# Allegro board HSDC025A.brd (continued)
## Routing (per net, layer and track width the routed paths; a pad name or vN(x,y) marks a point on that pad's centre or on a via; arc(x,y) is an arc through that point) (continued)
N53375: length 11.3
  TOP w0.14: C5.1 52.28,24.89 45.61,24.89 44.8,24.08 41.85,24.08 U1.40
N53379: length 11.3
  TOP w0.14: U1.39 41.85,23.82 44.9,23.82 45.72,24.64 52.28,24.64 C7.1
N53383: length 11.1
  TOP w0.14: U1.37 41.85,22.88 45.63,22.88 45.92,23.17 50.16,23.17 50.16,23.17 52.28,23.17 C10.1
N53387: length 11.1
  TOP w0.14: U1.36 41.85,22.62 45.73,22.62 46.02,22.91 50.06,22.91 50.06,22.91 52.28,22.91 C12.1
N53391: length 11.1
  TOP w0.14: U1.34 41.85,21.68 46.12,21.68 46.36,21.44 52.28,21.44 C14.1
N53395: length 11.1
  TOP w0.14: U1.33 41.85,21.42 46.02,21.42 46.25,21.19 52.28,21.19 C16.1
N53399: length 11.3
  TOP w0.14: U1.31 41.85,20.48 43.61,20.48 44.37,19.71 52.28,19.71 C18.1
N53403: length 11.3
  TOP w0.14: C20.1 52.28,19.46 44.27,19.46 43.51,20.22 41.85,20.22 U1.30
N54909: length 3.6
  BOTTOM w0.102: U6.K9 U6.L9 27.13,37.86 26.84,37.58 26.84,37.34 25.85,36.35
  BOTTOM w0.241: R37.1 25.45,35.94 25.85,36.35
N54981: length 2.6
  BOTTOM w0.102: U6.K10 U6.L10 26.63,37.86 25.54,36.78 R38.1
N60753: length 2
  BOTTOM w0.241: R22.1 18.27,7.77 18.31,7.81 J1.1
N61165: length 2.5
  BOTTOM w0.241: R28.1 27.86,7.83 27.9,7.88 J2.1
N61173: length 1.9
  BOTTOM w0.241: JMP3.4 46.18,41.33 46.21,41.36 R26.1
N61517: length 2
  BOTTOM w0.241: J3.1 35.71,7.92 35.69,7.9 R33.1
N61661: length 1.7
  BOTTOM w0.241: R35.1 10.6,7.82 10.62,7.8 J4.1
N62024: length 18.2
  TOP w0.14: v2(42.87,13.51) 42.78,13.6 42.78,14.03 43.72,14.97 46.66,14.97 48.22,16.53 51.54,16.53 R6.1 ; v2(41.63,16.29) 41.54,16.37 41.54,16.43 41.5,16.48 41.5,16.87 40.81,17.56 40.81,18.98 U1.27
  BOTTOM w0.14: v2(41.63,16.29) 41.54,16.2 41.54,15.91 41.78,15.67 42.15,15.67 42.56,15.27 42.56,14.87 42.96,14.47 R13.1 43.19,14.46 43.19,14.05 42.87,13.73 v2(42.87,13.51)
N62031: length 18.2
  TOP w0.14: v2(41.19,16.29) 41.19,16.3 41.24,16.35 41.24,16.76 40.55,17.46 40.55,18.98 U1.26 ; v2(42.44,13.51) 42.52,13.6 42.52,14.14 43.61,15.22 46.55,15.22 48.11,16.78 51.63,16.78 R8.1
  BOTTOM w0.14: v2(41.19,16.29) 41.28,16.2 41.28,15.81 41.68,15.42 42.05,15.42 42.3,15.16 42.3,14.96 42.14,14.8 R12.1 42.14,14.01 42.44,13.72 v2(42.44,13.51)
N62627: length 7.5
  TOP w0.241: U1.25 40.08,16.6 40.33,16.35 40.33,13.12 40.12,12.91 R11.2
N62636: length 4.3
  TOP w0.241: U1.24 39.68,17.7 39,17.02 R7.2
N63203: length 9.2
  TOP w0.241: R41.1 34.14,46.86 34.26,46.73 34.26,43.61 33.32,42.67 30.86,42.67 v2(30.18,41.99)
  BOTTOM w0.102: U6.B2 v2(30.18,41.99)
N63233: length 8
  TOP w0.241: R43.1 33,45.39 33.76,44.63 v2(33.76,43.89)
  BOTTOM w0.102: U6.C2 30.88,42.19 31.43,42.19 31.73,42.49 32.46,42.49 32.7,42.74 32.88,42.74 32.89,42.75
  BOTTOM w0.241: 32.89,42.75 33.16,42.75 33.76,43.35 v2(33.76,43.89)
N63241: length 5.4
  TOP w0.241: v1(22.38,41.77) 22.04,42.11 R44.1
  BOTTOM w0.102: 24.46,41.58 25.4,41.58 25.8,41.18 26.36,41.18 26.39,41.21 26.4,41.21 U6.D10
  BOTTOM w0.241: 24.46,41.58 22.57,41.58 v1(22.38,41.77)
N63249: length 15
  TOP w0.241: v2(27,41.94) 26.72,41.65 26.72,40.93 23.93,38.15 23.93,35.63 26.54,33.02 29.35,33.02 29.36,33.02 R40.2
  BOTTOM w0.102: U6.C10 v2(27,41.94)
N73513: length 21.9
  TOP w0.14: C1.2 49.23,38.62 49.23,36.56 47.42,34.75 41.64,34.75 39.19,32.3 39.19,26.09 38.81,25.71 38.81,24.92 U1.7
N73520: length 21.9
  TOP w0.14: U1.8 38.55,24.92 38.55,25.81 38.94,26.2 38.94,32.41 41.53,35 47.31,35 48.97,36.66 48.97,38.62 C9.2
N75829: length 5.4
  TOP w0.241: v1(22.45,39.98) R42.2
  BOTTOM w0.102: 24.46,40.78 25.13,40.78 25.22,40.69 26.38,40.69 U6.E10
  BOTTOM w0.241: v1(22.45,39.98) 23.25,40.78 24.46,40.78
N78382: length 1.8
  BOTTOM w0.241: R66.2 13.71,38.95 13.68,38.97 J7.1
N78490: length 1.7
  BOTTOM w0.241: J7.3 13.68,41.51 13.7,41.5 R70.2
N79273: length 9.2
  TOP w0.241: R49.2 37.17,35.95 36.74,35.52 31.82,35.52 v2(30.38,36.96)
  BOTTOM w0.102: U6.K3 30.38,38.18 v2(30.38,36.96)
N79277: length 9.5
  TOP w0.241: R48.2 31.62,34.9 v2(29.79,36.73)
  BOTTOM w0.102: v2(29.79,36.73) 29.79,37.06 30.13,37.39 U6.L3
N79281: length 4.9
  TOP w0.241: v2(33.9,36.65) R47.2
  BOTTOM w0.102: U6.K2 30.88,38.69 31.52,38.69 31.94,38.28 32.36,38.28 32.89,37.74 32.89,37.66
  BOTTOM w0.241: v2(33.9,36.65) 32.89,37.66
N79285: length 8
  TOP w0.241: v2(30.92,37.22) 32.06,36.09 35.45,36.09 36.4,37.03 R45.2
  BOTTOM w0.102: v2(30.92,37.22) 30.92,37.57 30.63,37.86 U6.L2
N80574: length 5.1
  TOP w0.241: R51.1 v1(22.4,38.91)
  BOTTOM w0.102: 24.46,40.34 24.56,40.44 U6.F11
  BOTTOM w0.241: v1(22.4,38.91) 23.83,40.34 24.46,40.34
N80581: length 4.8
  TOP w0.241: v1(22.43,40.88) 22.26,41.05 R50.1
  BOTTOM w0.102: U6.E11 25.5,40.94 25.21,41.23 24.46,41.23
  BOTTOM w0.241: 24.46,41.23 24.4,41.17 22.72,41.17 v1(22.43,40.88)
N81425: length 6.8
  TOP w0.241: v2(36.12,38.47) R39.1
  BOTTOM w0.102: 32.89,40.17 32.75,40.17 32.73,40.19 30.88,40.19 U6.G2
  BOTTOM w0.241: 32.89,40.17 32.92,40.17 34.63,38.46 v2(36.12,38.47)
N85567: length 6.5
  TOP w0.241: R53.2 36.61,40.62 36.26,40.62 v2(36.07,40.63)
  BOTTOM w0.102: 32.89,41.23 32.68,41.45 32.18,41.45 31.91,41.18 30.87,41.18 U6.E2
  BOTTOM w0.241: v2(36.07,40.63) 35.48,41.02 35.15,41.02 34.94,41.23 32.89,41.23
N85571: length 6.7
  TOP w0.241: R60.2 36.61,39.57 v2(36.07,39.57)
  BOTTOM w0.102: 32.89,40.86 32.6,40.86 32.44,40.69 30.88,40.69 U6.F2
  BOTTOM w0.241: v2(36.07,39.57) 34.58,40.86 32.89,40.86
N88590: length 7.3
  TOP w0.241: R87.1 22.16,37.6 v1(22.4,37.85) R52.1
  BOTTOM w0.102: 24.46,39.8 24.66,40.01 25.43,40.01 25.58,40.16 25.93,40.16 25.95,40.18 26.16,40.18 26.16,40.18 26.37,40.18 U6.F10
  BOTTOM w0.241: 24.46,39.8 24.36,39.8 v1(22.4,37.85)
N89051: length 2.3
  TOP w0.241: SW1.6 v1(15.6,56.16)
  BOTTOM w0.241: R62.1 16.12,56.16 16.12,56.16 v1(15.6,56.16)
N89058: length 2.3
  TOP w0.241: SW1.7 v1(15.6,54.89)
  BOTTOM w0.241: R63.1 16.12,54.89 16.12,54.89 v1(15.6,54.89)
N89065: length 2.3
  TOP w0.241: SW1.8 v1(15.57,53.62)
  BOTTOM w0.241: v1(15.57,53.62) 16.12,53.62 16.12,53.62 R64.1
N92164: length 3.2
  TOP w0.241: R61.1 28.64,44.13 28.63,44.12 v2(28.63,41.86)
  BOTTOM w0.102: U6.D6 v2(28.63,41.86)
N95070: length 1.3
  TOP w0.241: C27.1 28.12,39.47 28.13,39.47 v2(28.13,39.07)
  BOTTOM w0.102: U6.H7 v2(28.13,39.07)
N98885: length 1.6
  TOP w0.241: D2.2 54.03,38.2 54.15,38.32 R77.1
N16698171: length 4
  TOP w0.241: v1(57.51,35.15) 57.61,35.26 FB1.1
  BOTTOM w0.241: R75.2 58.47,36.12 v1(57.51,35.15) 56.59,36.07 R76.2
N16698282: length 4.4
  TOP w0.241: R46.1 27.41,37.29 28.63,38.51 v2(28.63,39.09)
  BOTTOM w0.102: U6.H6 v2(28.63,39.09)
N16700173: length 2.2
  TOP w0.241: R78.1 62.15,60.93 61.67,61.42 D4.2
N16705873: length 14.5
  TOP w0.14: U1.12 37.91,22.88 29.46,22.88 29.04,22.46 24.14,22.46 23.85,22.75 C8.2
N16705894: length 14.5
  TOP w0.14: C11.2 23.85,21.91 24.14,22.2 29.14,22.2 29.56,22.62 37.9,22.62 U1.13
N16705898: length 14.7
  TOP w0.14: C13.2 24.15,20.73 29.62,20.73 30.57,21.68 37.91,21.68 U1.15
N16705902: length 14.7
  TOP w0.14: U1.16 37.9,21.42 30.67,21.42 29.73,20.48 24.15,20.48 C15.2
N16750118: length 3.6
  BOTTOM w0.241: U9.5 69.57,37.81 69.48,37.91 R81.1 R80.2
N16816893: length 2
  BOTTOM w0.241: R19.1 15.97,17.09 15.94,17.12 JMP1.2
N16816902: length 2.1
  BOTTOM w0.241: R21.1 16,14.52 15.94,14.58 JMP1.4
N16816999: length 1.9
  BOTTOM w0.241: R24.1 46.2,43.84 46.18,43.87 JMP3.2
N16817208: length 2.1
  BOTTOM w0.241: R29.1 58.79,8.31 58.71,8.38 JMP5.2
N16817217: length 2.1
  BOTTOM w0.241: JMP5.4 58.71,5.84 58.79,5.77 R31.1
N16817279: length 2
  BOTTOM w0.241: JMP7.2 48.49,8.38 48.51,8.37 R34.1
N16817288: length 1.9
  BOTTOM w0.241: R36.1 48.56,5.77 48.49,5.84 JMP7.4
N16817349: length 1.5
  BOTTOM w0.241: R30.1 68.31,8.31 68.23,8.38 JMP6.2
N16817418: length 1.5
  BOTTOM w0.241: R32.1 68.67,5.95 68.23,5.84 JMP6.4
N16817489: length 2
  BOTTOM w0.241: JMP4.4 43.95,53.05 44,53 R27.1
N16817492: length 2
  BOTTOM w0.241: JMP4.2 43.95,55.59 44.1,55.43 R25.1
N16817504: length 2.1
  BOTTOM w0.241: R20.1 28.74,17.95 28.67,17.88 JMP2.2
N16817513: length 1.7
  BOTTOM w0.241: JMP2.4 29.66,14.35 29.71,14.3 R23.1

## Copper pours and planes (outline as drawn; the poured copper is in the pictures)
GND on TOP: 31.55,37.19 31.55,37.65 31.91,38.01 32.95,38.01 33.25,38.3 33.25,38.66 33.99,38.66 34.37,39.04 35.67,39.04 35.67,37.39 35.23,36.96 34.67,36.96 34.62,37.01 34.62,37.95 34.52,38.05 33.48,38.05 32.59,37.16 31.57,37.16
GND on TOP: 37.92,34.62 37.92,37.62 37.39,38.15 37.39,40.94 39.22,40.94 39.22,34.59 37.95,34.59
GND on TOP: 24.62,45.2 24.62,44.59 23.93,43.9 23.93,41.3 22.97,41.3 22.97,45.2
GND on TOP: 57.4,42.96 53.45,42.96 52.86,42.37 52.86,40.72 53.87,39.7 54.48,39.7 55.98,41.2 55.98,41.22 57.4,41.22
GND on BOTTOM: 68.49,34.78 71.66,34.78 72.44,35.56 72.44,38.16 71.4,39.2 67.45,39.2 67,38.75 65.98,38.75 65.48,39.25 65.48,43.03 67.18,44.73 77.17,44.73 77.92,43.98 77.92,31.76 77.94,31.74 77.94,28.01 77.17,27.24 66.61,27.24 65.45,28.4 65.45,30.76 71.56,30.76 71.93,31.13 71.93,33.28 71.05,34.15 68.47,34.15 68.47,34.76
GND on BOTTOM: 7.92,26.98 1.43,26.98 0.68,26.22 0.68,16.4 1.14,15.93 7.17,15.93 8.3,17.06 8.3,18.02 7.88,18.44 4.18,18.44 4.18,24.44 4.81,25.06 7.87,25.06 7.97,25.16 7.97,26.93
GND on BOTTOM: 57.81,40.82 54.79,40.82 52.37,38.4 48.54,38.4 48.44,38.51 48.44,45.29 48.49,45.34 50.7,45.34 54.61,41.43 57.78,41.43 57.81,41.4
GND on BOTTOM: 27.48,42.57 27.48,41.91 27.05,41.48 27.05,39.78 27.43,39.78 27.48,39.73 27.48,39.27 27.43,39.22 27.05,39.22 27.05,38.91 27.79,38.91 27.79,39.8 28.98,39.8 28.98,38.91 29.79,38.91 29.79,39.57 29.36,39.57 29.26,39.67 29.26,40.87 29.26,40.87 29.26,41.01 29.2,41.07 27.76,41.07 27.76,42.57
GND on L2_GND, L5_GND: 0.64,0.64 0.64,67.74 79.12,67.74 79.12,0.64 ; 10 cut-outs
VBUS on TOP: 25.04,45.16 25.04,44.37 24.77,44.09 24.77,42.94 25.03,42.94 25.04,42.94 27,42.94 27,45.16
VBUS on TOP: 4.34,33.55 4.34,31.68 8.63,31.68 8.63,33.55
VBUS on BOTTOM: 0.98,67.39 15.56,67.39 15.56,67.39 17.81,67.39 17.81,65.24 17.73,65.17 15.93,65.17 14.61,63.85 14.61,56.76 12.67,54.83 9.76,54.83 8.54,53.61 8.54,31.7 0.98,31.7
VBUS on BOTTOM: 26.29,39.52 26.29,39.12 26.34,39.07 26.77,39.07 26.77,38.79 26.75,38.76 26.29,38.76 26.29,38.35 25.2,38.35 25.2,38.99 25.43,38.99 25.96,39.52
VBUS on BOTTOM: 26.77,42.29 26.77,43.26 27,43.48 27,43.79 26.24,43.79 26.24,43.51 26.49,43.26 26.49,42.29
VBUS on BOTTOM: 65.52,35.06 65.52,37.85 63.16,37.85 63.16,35.06
VBUS on L3_PWR: 18.31,37.41 19.23,36.5 21.49,36.5 23.87,38.88 23.87,41.42 26.19,41.42 26.19,43.83 26.16,43.86 26.16,47.52 34.85,56.2 62.75,56.2 64.04,54.91 64.04,39.7 65.38,38.37 65.38,36.6 65.31,36.54 62.09,36.54 61.44,37.19 61.44,40.11 49.72,51.83 34.14,51.83 27.03,44.71 27.03,36.35 25.15,34.47 14.4,34.47 14.39,34.46 8.73,34.46 8.62,34.35 8.62,31.63 4.38,31.63 4.31,31.69 4.31,36.46 5.27,37.41
VBUS_DS on TOP: 24.68,42.72 24.68,41.29 25.84,41.29 25.84,42.72
VBUS_DS on BOTTOM: 70.68,36.01 68.25,36.01 68.03,36.24 68.03,37.96 68.03,37.96 66.01,37.96 66,37.95 66,35.57 66.52,35.05 66.52,35.06 67.79,35.06 68.15,35.42 70.69,35.42 70.69,36
VBUS_DS on BOTTOM: 26.29,43.1 26.29,41.35 26.01,41.35 25.22,42.14 25.21,42.14 25.21,43.1
VBUS_DS on L3_PWR: 0.71,62.58 0.71,67.59 78.94,67.59 79.03,67.49 79.03,35.74 78.97,35.68 65.93,35.68 65.93,39.32 64.78,40.47 64.78,57.22 35.09,57.22 25.82,47.95 25.82,41.78 23.93,41.78 23.93,57.82 19.17,62.58 ; 8 cut-outs
VBUS_DS on L4_PWR: 24.84,40.72 26.21,39.34 27.15,39.34 27.23,39.42 27.23,39.6 27.15,39.67 26.72,39.67 25.84,40.55 25.84,43 25.71,43.14 24.92,43.14 24.84,43.06
VDDIO on L3_PWR: 32.48,43.66 32.48,41.98 31.68,41.18 31.68,39.01 34.56,36.13 34.56,30.73 31.96,30.73 31.04,31.66 31.04,43.25 31.49,43.7 32.44,43.7
VDDIO on L4_PWR: 51.2,32.9 51.2,30.3 50.72,29.81 41.55,29.81 36.27,35.09 34.04,35.09 32.7,33.76 32.7,31.82 37.22,27.3 51.55,27.3 53,28.76 53,33.32 52.99,33.33 51.63,33.33
3P3VCC on TOP: 55.55,36.68 55.55,40.16 58.52,40.16 58.52,37.37 56.59,37.37 56.59,36.68
3P3VCC on BOTTOM: 55.52,40.16 55.52,37.36 58.52,37.36 58.52,40.16
3P3VCC on L4_PWR: 57.31,40.41 57.31,35.38 62.21,30.47 62.21,16.79 61.61,16.19 41.09,16.19 40.4,15.5 40.4,13.87 41.01,13.26 64.19,13.26 65.53,14.6 65.53,32.02 60.45,37.1 60.45,40.37 60.41,40.41 ; 2 cut-outs
1064_VCC on BOTTOM: 57.73,34.06 57.73,30.05 59.55,30.05 59.55,34.06
1064_VCC on L3_PWR: 78.89,1.09 78.89,35.39 78.73,35.22 60.7,35.22 60.7,39.73 49.38,51.05 39.11,51.05 39.11,48.36 43.35,48.36 43.74,48.75 48.97,48.75 48.97,44.13 46.04,44.13 46.03,41.59 47.42,41.59 50.45,41.59 56.09,35.95 56.17,35.95 56.17,30.99 44.98,30.99 44.98,37.13 44.7,37.41 42.75,37.41 42.25,36.92 42.32,36.86 42.32,33.93 35.36,33.93 35.36,29.44 22.45,16.53 0.94,16.53 0.94,1.09 ; 1 cut-out
LDO_3P3 on TOP: 19.71,44.42 19.71,45.9 24.82,45.9 25.27,46.35 29.08,46.35 29.08,45.36 28.02,45.36 27.76,45.62 27.05,45.62 26.88,45.45 22.77,45.45 22.33,45.01 22.33,44.5 22.25,44.42
LDO_3P3 on L3_PWR: 10.79,53.54 10.79,46.28 20.08,36.99 20.82,36.99 23,39.16 23,50.39 19.85,53.54
LDO_3P3 on L4_PWR: 44.23,30.37 42.64,31.96 42.64,34 39.65,36.99 39.65,38.66 32.97,38.66 32.49,39.14 32.49,40.36 32.99,40.87 36.14,40.87 36.68,41.4 36.68,44.45 35.97,45.16 28.3,45.16 27.61,45.85 27.61,46.66 28.07,47.12 36.75,47.12 38.97,44.9 44.36,44.9 44.36,36.67 47.87,33.16 50.13,33.16 50.82,32.47 50.84,32.47 50.84,30.9 50.3,30.37
SYS_PWR on TOP: 16.14,61.71 16.14,43.05 17.99,43.05 17.99,61.71
SYS_PWR on TOP: 59.98,59.95 59.98,55.47 61.41,55.47 61.41,59.95
SYS_PWR on BOTTOM: 16.12,44.36 19.25,44.36 19.58,44.02 22.21,44.02 22.86,43.38 23.53,43.38 24.86,44.71 28.16,44.71 28.65,44.22 28.65,43.62 27.61,43.62 27.58,43.65 27.58,43.85 27.41,44.01 25.65,44.01 24.19,42.55 16.32,42.55 16.12,42.75
SYS_PWR on BOTTOM: 55.52,45.06 55.52,42.04 57.78,42.04 59.13,40.69 59.13,39.82 59.17,39.82 59.17,38.45 60.48,37.14 60.48,31.57 70.76,31.57 70.78,31.59 70.78,33.48 70.76,33.5 68.39,33.5 68.16,33.74 63.49,33.74 62.24,34.99 62.24,38.88 61.3,39.82 61.3,47.25 61.35,47.3 61.35,57.9 60,57.9 59.98,57.87 59.98,47.34 60.04,47.27 55.52,47.27 55.5,47.29 52.5,47.29 51.46,48.34 46.46,48.34 46.46,47.07 50.44,47.07 52.43,45.09 55.5,45.09
SYS_PWR on BOTTOM: 27.53,42.82 27.61,42.75 27.86,42.75 27.99,42.62 27.99,42.37 28.07,42.29 28.22,42.29 28.27,42.34 28.27,42.65 28.37,42.75 28.65,42.75 28.73,42.82 28.73,43.05 28.65,43.13 28.65,43.69 28.55,43.79 27.69,43.79 27.58,43.69 27.58,43.13 27.53,43.08
SYS_PWR on L3_PWR: 30.61,42.89 30.61,43.98 31.55,44.92 31.55,44.93 48.38,44.93 48.38,48.33 43.81,48.33 43.11,47.63 30.65,47.63 27.51,44.49 27.51,42.89
TPS65986_3P3V on BOTTOM: 57.18,34.06 57.18,31.06 53.31,31.06 53.31,34.06
TPS65986_3P3V on L3_PWR: 46.81,32.08 46.81,38.23 42.37,38.23 40.69,36.55 34.65,36.55 32.05,39.14 32.05,40.26 49.81,40.26 55.5,34.57 55.47,34.57 55.47,32.21 55.4,32.13 49.38,32.13 49.35,32.11 49.35,32.08
N51428 on TOP: 7.92,30.94 7.92,27.3 4.76,27.3 4.76,30.94
N51428 on L3_PWR: 9.71,30.95 9.71,23.39 7.83,21.5 7.83,20.13 6.06,20.13 6.06,27.29 6.02,27.26 4.74,27.26 4.74,30.96 4.76,30.98 4.79,30.95
N16697259 on BOTTOM: 49.33,51.08 51.51,51.08 51.99,51.56 51.99,55.83 53.06,56.9 55.96,56.9 56.52,56.34 56.52,49.76 56.26,49.5 51.94,49.5 51.59,49.86 49.35,49.86 49.33,49.89

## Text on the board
BOTTOM: LAYER 4 - BOTTOM SIDE
Board Geometry/Soldermask Bottom: SOLDERMASK BOTTOM
Package Geometry/Pastemask Bottom: PASTEMASK BOTTOM
Ref Des/Silkscreen Bottom: FOR EVALUATION ONLY. NOT FCC APPROVED FOR RESALE | SILKSCREEN BOTTOM
TOP: LAYER 1 - TOP SIDE
Board Geometry/Soldermask Top: SOLDERMASK TOP
Package Geometry/Pastemask Top: PASTEMASK TOP
Ref Des/Silkscreen Top: UFP | CC2 | CC1 | VBUS_DS | SYS_PWR | R | VBUS | VCC | EN | GND | EQ1 | 1 | 0 | /SCL | FLIP | DBG_CTL2 | I2C_ADDR | DBG_CTL1 | EQ0 | CTL0 | /SDA | CTL1 | SSEQ0/A0 | SSEQ1 | I2C | DPEQ1 | DPEQ0/A1 | N/C | PROGRAMMING | SPI | GPIO8 | GPIO6 | GPIO7 | HPD | GPIO5 | GPIO3 | SCL | CTLO | SDA | HSDC025A | LB2 | SILKSCREEN TOP | +5V IN
L2_GND: LAYER 2 - GND PLANE
L5_GND: LAYER 3 - PWR PLANE
XSECTION_CHART: * AIR 0 MIL | * SOLDERMASK-0.8MIL 0.8 MIL | L1: COPPER_1/2OZ_PLATED 1.4 MIL | * FILL_0.150 5.91 MIL | L2: COPPER_1.0OZ 1.4 MIL | * FILL_0.250 9.84 MIL | L3: COPPER_1.0OZ 1.4 MIL | * CORE_0.500 19.69 MIL | L4: COPPER_1.0OZ 1.4 MIL | L5: COPPER_1.0OZ 1.4 MIL | L6: COPPER_1/2OZ_PLATED 1.4 MIL | DESIGN CROSS SECTION CHART | ___________________________ | TOTAL THICKNESS 61.19 MIL | 1-6
DIMENSION: FABRICATION DRAWING | CAD ORIGIN
User.6: LAYER 1 | LAYER 2 | LAYER 3 | LAYER 4 | LAYER 5 | LAYER 6 | LAYER | NO. | TABLE 1: | TOP | L2_GND | L3_PWR | L4_PWR | L5_GND | BOTTOM | NAME | DIFFIRENTIAL PAIR | IMPEDANCE (OHMS) | 90  +/- 10% | DIFF TRACE | WIDTH | 0.0055" | SPACING | 0.0045" | SINGLE ENDED | 50 +/- 10% | TRACE WIDTH | 0.0095" | REFERENCE | SPECIAL FAB NOTES: | PLACE DRILL CHART HERE: | 1:FAB SHOP MUST FOLLOW THE SOLDER MASK REVIEW LAYERS. | 2: | MIN. ANNULAR RING 2 MIL EXTERNAL PER IPC-6012C CLASS 2 | REGISTRATION TOLERANCES: METAL +/- X MIL,HOLES +/- X MIL | IMPEDANCE CONTROL: | BOARD SIZE (REFER ALSO ARRAY/PANEL PROFILING INFORMATION) | MIXED DIELECTRIC: | LAMINATE MATERIAL: | THICKNESS: | TOLERANCE: | COPPER THICKNESS (FINISHED): | BOARD FINISH: | NUMBER OF LAYERS: | MIN. TRACK WIDTH: | MIN. CLEARANCE  : | MIN. VIA PAD/DRILL: | THIEVING ALLOWED: | X | OUTER: | INNER SIGNAL: | INNER PLANE: | OTHER: | SILKSCREEN: | SOLDERMASK: (PER IPC-6011,6012) | BOARD SURFACE TREATMENT: | ADDITIONAL REQUIREMENTS: | VENDOR MARKING: | SILKSCREEN COLOR: | SOLDERMASK COLOR: | THROUGH-HOLE VIA TREATMENT: | VIA FILL USING NON-CONDUCTIVE EPOXY: | FOR WIRE BONDING: | VENDOR DATE CODE,UL,LOGO: | FR-4 HIGH Tg | 0.062" +/-10% | IPC-6012C TYPE 3 CLASS 2 | OTHER +/- | MICRO-SECTION | CERTIFICATES OF COMPLIANCE | NICKEL/GOLD (ENIG) | IMMERSION TIN | HARD GOLD | IN AN OPEN AREA | 1/4 OZ. | OPEN | NO | 6 | 5.5 MIL | 4.5 MIL | 12/06 MIL | NONE | DESIGN INFORMATION | ROGERS 4350B | 0.093" +/-10% | YES | TDR REPORTS/COUPONS | WHITE | GREEN | SOFT GOLD | TENTED | 1/2 OZ. | BOW & TWIST: | ORGANIC (OSP) | OTHER | WHERE INDICATED (SEE DRAWING) | YES - SEE TABLE 1 | ETCH | IDENTIFIER: | BLUE | RoHS | 1.0 OZ. | SILKSCREEN | PER SUPPLIED ARTWORK | ALL x MIL VIAS | ELECTRICAL TEST | UL 94V-0 | HASL | 2.0 OZ. | BREAK-AWAY | ENEPIG
User.10: FIGURE | SIZE | 6.0 | 8.0 | 10.0 | 28.0 | 38.0 | 91.0 | 120.0 | 140.0 | 23.62 | 33.46 | 55.12 | 67.0 | 125.0 | 49.21x27.56 | 66.93x23.62 | 74.8x23.62 | 78.74x27.56 | 86.61x23.62 | 33.46x19.69 | DRILL CHART: TOP to BOTTOM | ALL UNITS ARE IN MILS | TOLERANCE | +3.0/-3.0 | +2.0/-2.0 | PLATED | NON-PLATED | QTY | 112 | 8 | 190 | 9 | 74 | 10 | 2 | 1 | 4
